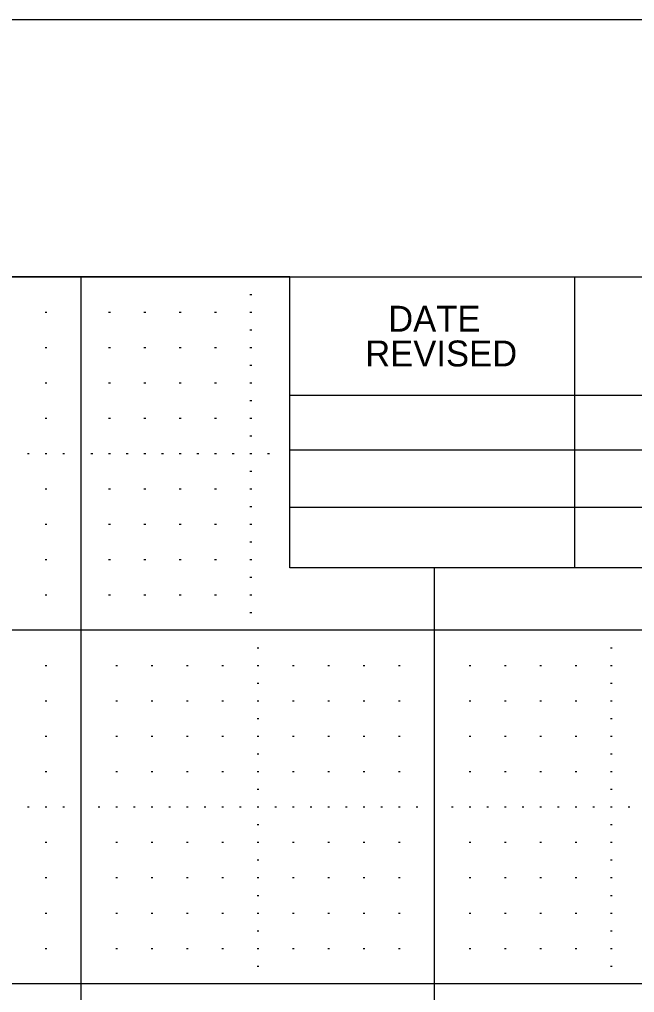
# Model space of a CAD drawing. Extents: x -1.6 to 32.4, y -1.9 to 21.6.
# Drawn here: x 25.633 to 27.374, y 18.52 to 21.273 of the extents above; entities that cross this region are included whole.
import ezdxf

# ---------------------------------------------------------------- set-up
doc = ezdxf.new("R2010")
doc.units = 0
for name, color, linetype in [('Level 1', 7, 'Continuous'), ('Level 4', 7, 'Continuous'), ('Level 5', 7, 'Continuous'), ('Level 61', 7, 'Continuous'), ('Level 63', 7, 'Continuous')]:
    doc.layers.add(name, color=color, linetype=linetype)

msp = doc.modelspace()

# ---------------------------------------------------------------- linework, layer by layer
at = {"layer": 'Level 1'}
for p, q in [((-0.001, 20.545), (31.617, 20.545)), ((26.3984, 19.7217), (26.3984, 20.545)), ((27.2051, 19.7217), (27.2051, 20.545)), ((26.3984, 20.21), (28.0268, 20.21)), ((26.3984, 20.055), (28.0268, 20.055)), ((26.3984, 19.8933), (28.0268, 19.8933)), ((31.6184, 19.7217), (26.3984, 19.7217))]:
    msp.add_line(p, q, dxfattribs=at)
at = {"layer": 'Level 4'}
for p, q in [((25.808, 0.545), (25.808, 20.545)), ((26.808, 0.545), (26.808, 19.7217)), ((31.617, 19.545), (-0.001, 19.545)), ((31.617, 18.545), (-0.001, 18.545))]:
    msp.add_line(p, q, dxfattribs=at)
at = {"layer": 'Level 5'}
for p, q in [((26.2855, 20.495), (26.2905, 20.495)), ((25.7055, 20.445), (25.7105, 20.445)), ((25.8855, 20.445), (25.8905, 20.445)), ((25.9855, 20.445), (25.9905, 20.445)), ((26.0855, 20.445), (26.0905, 20.445)), ((26.1855, 20.445), (26.1905, 20.445)), ((26.2855, 20.445), (26.2905, 20.445)), ((26.2855, 20.395), (26.2905, 20.395)), ((25.7055, 20.345), (25.7105, 20.345)), ((25.8855, 20.345), (25.8905, 20.345)), ((25.9855, 20.345), (25.9905, 20.345)), ((26.0855, 20.345), (26.0905, 20.345)), ((26.1855, 20.345), (26.1905, 20.345)), ((26.2855, 20.345), (26.2905, 20.345)), ((26.2855, 20.295), (26.2905, 20.295)), ((25.7055, 20.245), (25.7105, 20.245)), ((25.8855, 20.245), (25.8905, 20.245)), ((25.9855, 20.245), (25.9905, 20.245)), ((26.0855, 20.245), (26.0905, 20.245)), ((26.1855, 20.245), (26.1905, 20.245)), ((26.2855, 20.245), (26.2905, 20.245)), ((26.2855, 20.195), (26.2905, 20.195)), ((25.7055, 20.145), (25.7105, 20.145)), ((25.8855, 20.145), (25.8905, 20.145)), ((25.9855, 20.145), (25.9905, 20.145)), ((26.0855, 20.145), (26.0905, 20.145)), ((26.1855, 20.145), (26.1905, 20.145)), ((26.2855, 20.145), (26.2905, 20.145)), ((26.2855, 20.095), (26.2905, 20.095)), ((25.6555, 20.045), (25.6605, 20.045)), ((25.7055, 20.045), (25.7105, 20.045)), ((25.7555, 20.045), (25.7605, 20.045)), ((25.8355, 20.045), (25.8405, 20.045)), ((25.8855, 20.045), (25.8905, 20.045)), ((25.9355, 20.045), (25.9405, 20.045)), ((25.9855, 20.045), (25.9905, 20.045)), ((26.0355, 20.045), (26.0405, 20.045)), ((26.0855, 20.045), (26.0905, 20.045)), ((26.1355, 20.045), (26.1405, 20.045)), ((26.1855, 20.045), (26.1905, 20.045)), ((26.2355, 20.045), (26.2405, 20.045)), ((26.2855, 20.045), (26.2905, 20.045)), ((26.3355, 20.045), (26.3405, 20.045)), ((26.2855, 19.995), (26.2905, 19.995)), ((25.7055, 19.945), (25.7105, 19.945)), ((25.8855, 19.945), (25.8905, 19.945)), ((25.9855, 19.945), (25.9905, 19.945)), ((26.0855, 19.945), (26.0905, 19.945)), ((26.1855, 19.945), (26.1905, 19.945)), ((26.2855, 19.945), (26.2905, 19.945)), ((26.2855, 19.895), (26.2905, 19.895)), ((25.7055, 19.845), (25.7105, 19.845)), ((25.8855, 19.845), (25.8905, 19.845)), ((25.9855, 19.845), (25.9905, 19.845)), ((26.0855, 19.845), (26.0905, 19.845)), ((26.1855, 19.845), (26.1905, 19.845)), ((26.2855, 19.845), (26.2905, 19.845)), ((26.2855, 19.795), (26.2905, 19.795)), ((25.7055, 19.745), (25.7105, 19.745)), ((25.8855, 19.745), (25.8905, 19.745)), ((25.9855, 19.745), (25.9905, 19.745)), ((26.0855, 19.745), (26.0905, 19.745)), ((26.1855, 19.745), (26.1905, 19.745)), ((26.2855, 19.745), (26.2905, 19.745)), ((26.2855, 19.695), (26.2905, 19.695)), ((25.7055, 19.645), (25.7105, 19.645)), ((25.8855, 19.645), (25.8905, 19.645)), ((25.9855, 19.645), (25.9905, 19.645)), ((26.0855, 19.645), (26.0905, 19.645)), ((26.1855, 19.645), (26.1905, 19.645)), ((26.2855, 19.645), (26.2905, 19.645)), ((26.2855, 19.595), (26.2905, 19.595)), ((26.3055, 19.495), (26.3105, 19.495)), ((27.3055, 19.495), (27.3105, 19.495)), ((25.7055, 19.445), (25.7105, 19.445)), ((25.9055, 19.445), (25.9105, 19.445)), ((26.0055, 19.445), (26.0105, 19.445)), ((26.1055, 19.445), (26.1105, 19.445)), ((26.2055, 19.445), (26.2105, 19.445)), ((26.3055, 19.445), (26.3105, 19.445)), ((26.4055, 19.445), (26.4105, 19.445)), ((26.5055, 19.445), (26.5105, 19.445)), ((26.6055, 19.445), (26.6105, 19.445)), ((26.7055, 19.445), (26.7105, 19.445)), ((26.9055, 19.445), (26.9105, 19.445)), ((27.0055, 19.445), (27.0105, 19.445)), ((27.1055, 19.445), (27.1105, 19.445)), ((27.2055, 19.445), (27.2105, 19.445)), ((27.3055, 19.445), (27.3105, 19.445)), ((26.3055, 19.395), (26.3105, 19.395)), ((27.3055, 19.395), (27.3105, 19.395)), ((25.7055, 19.345), (25.7105, 19.345)), ((25.9055, 19.345), (25.9105, 19.345)), ((26.0055, 19.345), (26.0105, 19.345)), ((26.1055, 19.345), (26.1105, 19.345)), ((26.2055, 19.345), (26.2105, 19.345)), ((26.3055, 19.345), (26.3105, 19.345)), ((26.4055, 19.345), (26.4105, 19.345)), ((26.5055, 19.345), (26.5105, 19.345)), ((26.6055, 19.345), (26.6105, 19.345)), ((26.7055, 19.345), (26.7105, 19.345)), ((26.9055, 19.345), (26.9105, 19.345)), ((27.0055, 19.345), (27.0105, 19.345)), ((27.1055, 19.345), (27.1105, 19.345)), ((27.2055, 19.345), (27.2105, 19.345)), ((27.3055, 19.345), (27.3105, 19.345)), ((26.3055, 19.295), (26.3105, 19.295)), ((27.3055, 19.295), (27.3105, 19.295)), ((25.7055, 19.245), (25.7105, 19.245)), ((25.9055, 19.245), (25.9105, 19.245)), ((26.0055, 19.245), (26.0105, 19.245)), ((26.1055, 19.245), (26.1105, 19.245)), ((26.2055, 19.245), (26.2105, 19.245)), ((26.3055, 19.245), (26.3105, 19.245)), ((26.4055, 19.245), (26.4105, 19.245)), ((26.5055, 19.245), (26.5105, 19.245)), ((26.6055, 19.245), (26.6105, 19.245)), ((26.7055, 19.245), (26.7105, 19.245)), ((26.9055, 19.245), (26.9105, 19.245)), ((27.0055, 19.245), (27.0105, 19.245)), ((27.1055, 19.245), (27.1105, 19.245)), ((27.2055, 19.245), (27.2105, 19.245)), ((27.3055, 19.245), (27.3105, 19.245)), ((26.3055, 19.195), (26.3105, 19.195)), ((27.3055, 19.195), (27.3105, 19.195)), ((25.7055, 19.145), (25.7105, 19.145)), ((25.9055, 19.145), (25.9105, 19.145)), ((26.0055, 19.145), (26.0105, 19.145)), ((26.1055, 19.145), (26.1105, 19.145)), ((26.2055, 19.145), (26.2105, 19.145)), ((26.3055, 19.145), (26.3105, 19.145)), ((26.4055, 19.145), (26.4105, 19.145)), ((26.5055, 19.145), (26.5105, 19.145)), ((26.6055, 19.145), (26.6105, 19.145)), ((26.7055, 19.145), (26.7105, 19.145)), ((26.9055, 19.145), (26.9105, 19.145)), ((27.0055, 19.145), (27.0105, 19.145)), ((27.1055, 19.145), (27.1105, 19.145)), ((27.2055, 19.145), (27.2105, 19.145)), ((27.3055, 19.145), (27.3105, 19.145)), ((26.3055, 19.095), (26.3105, 19.095)), ((27.3055, 19.095), (27.3105, 19.095)), ((25.6555, 19.045), (25.6605, 19.045)), ((25.7055, 19.045), (25.7105, 19.045)), ((25.7555, 19.045), (25.7605, 19.045)), ((25.8555, 19.045), (25.8605, 19.045)), ((25.9055, 19.045), (25.9105, 19.045)), ((25.9555, 19.045), (25.9605, 19.045)), ((26.0055, 19.045), (26.0105, 19.045)), ((26.0555, 19.045), (26.0605, 19.045)), ((26.1055, 19.045), (26.1105, 19.045)), ((26.1555, 19.045), (26.1605, 19.045)), ((26.2055, 19.045), (26.2105, 19.045)), ((26.2555, 19.045), (26.2605, 19.045)), ((26.3055, 19.045), (26.3105, 19.045)), ((26.3555, 19.045), (26.3605, 19.045)), ((26.4055, 19.045), (26.4105, 19.045)), ((26.4555, 19.045), (26.4605, 19.045)), ((26.5055, 19.045), (26.5105, 19.045)), ((26.5555, 19.045), (26.5605, 19.045)), ((26.6055, 19.045), (26.6105, 19.045)), ((26.6555, 19.045), (26.6605, 19.045)), ((26.7055, 19.045), (26.7105, 19.045)), ((26.7555, 19.045), (26.7605, 19.045)), ((26.8555, 19.045), (26.8605, 19.045)), ((26.9055, 19.045), (26.9105, 19.045)), ((26.9555, 19.045), (26.9605, 19.045)), ((27.0055, 19.045), (27.0105, 19.045)), ((27.0555, 19.045), (27.0605, 19.045)), ((27.1055, 19.045), (27.1105, 19.045)), ((27.1555, 19.045), (27.1605, 19.045)), ((27.2055, 19.045), (27.2105, 19.045)), ((27.2555, 19.045), (27.2605, 19.045)), ((27.3055, 19.045), (27.3105, 19.045)), ((27.3555, 19.045), (27.3605, 19.045)), ((26.3055, 18.995), (26.3105, 18.995)), ((27.3055, 18.995), (27.3105, 18.995)), ((25.7055, 18.945), (25.7105, 18.945)), ((25.9055, 18.945), (25.9105, 18.945)), ((26.0055, 18.945), (26.0105, 18.945)), ((26.1055, 18.945), (26.1105, 18.945)), ((26.2055, 18.945), (26.2105, 18.945)), ((26.3055, 18.945), (26.3105, 18.945)), ((26.4055, 18.945), (26.4105, 18.945)), ((26.5055, 18.945), (26.5105, 18.945)), ((26.6055, 18.945), (26.6105, 18.945)), ((26.7055, 18.945), (26.7105, 18.945)), ((26.9055, 18.945), (26.9105, 18.945)), ((27.0055, 18.945), (27.0105, 18.945)), ((27.1055, 18.945), (27.1105, 18.945)), ((27.2055, 18.945), (27.2105, 18.945)), ((27.3055, 18.945), (27.3105, 18.945)), ((26.3055, 18.895), (26.3105, 18.895)), ((27.3055, 18.895), (27.3105, 18.895)), ((25.7055, 18.845), (25.7105, 18.845)), ((25.9055, 18.845), (25.9105, 18.845)), ((26.0055, 18.845), (26.0105, 18.845)), ((26.1055, 18.845), (26.1105, 18.845)), ((26.2055, 18.845), (26.2105, 18.845)), ((26.3055, 18.845), (26.3105, 18.845)), ((26.4055, 18.845), (26.4105, 18.845)), ((26.5055, 18.845), (26.5105, 18.845)), ((26.6055, 18.845), (26.6105, 18.845)), ((26.7055, 18.845), (26.7105, 18.845)), ((26.9055, 18.845), (26.9105, 18.845)), ((27.0055, 18.845), (27.0105, 18.845)), ((27.1055, 18.845), (27.1105, 18.845)), ((27.2055, 18.845), (27.2105, 18.845)), ((27.3055, 18.845), (27.3105, 18.845)), ((26.3055, 18.795), (26.3105, 18.795)), ((27.3055, 18.795), (27.3105, 18.795)), ((25.7055, 18.745), (25.7105, 18.745)), ((25.9055, 18.745), (25.9105, 18.745)), ((26.0055, 18.745), (26.0105, 18.745)), ((26.1055, 18.745), (26.1105, 18.745)), ((26.2055, 18.745), (26.2105, 18.745)), ((26.3055, 18.745), (26.3105, 18.745)), ((26.4055, 18.745), (26.4105, 18.745)), ((26.5055, 18.745), (26.5105, 18.745)), ((26.6055, 18.745), (26.6105, 18.745)), ((26.7055, 18.745), (26.7105, 18.745)), ((26.9055, 18.745), (26.9105, 18.745)), ((27.0055, 18.745), (27.0105, 18.745)), ((27.1055, 18.745), (27.1105, 18.745)), ((27.2055, 18.745), (27.2105, 18.745)), ((27.3055, 18.745), (27.3105, 18.745)), ((26.3055, 18.695), (26.3105, 18.695)), ((27.3055, 18.695), (27.3105, 18.695)), ((25.7055, 18.645), (25.7105, 18.645)), ((25.9055, 18.645), (25.9105, 18.645)), ((26.0055, 18.645), (26.0105, 18.645)), ((26.1055, 18.645), (26.1105, 18.645)), ((26.2055, 18.645), (26.2105, 18.645)), ((26.3055, 18.645), (26.3105, 18.645)), ((26.4055, 18.645), (26.4105, 18.645)), ((26.5055, 18.645), (26.5105, 18.645)), ((26.6055, 18.645), (26.6105, 18.645)), ((26.7055, 18.645), (26.7105, 18.645)), ((26.9055, 18.645), (26.9105, 18.645)), ((27.0055, 18.645), (27.0105, 18.645)), ((27.1055, 18.645), (27.1105, 18.645)), ((27.2055, 18.645), (27.2105, 18.645)), ((27.3055, 18.645), (27.3105, 18.645)), ((26.3055, 18.595), (26.3105, 18.595)), ((27.3055, 18.595), (27.3105, 18.595))]:
    msp.add_line(p, q, dxfattribs=at)
at = {"layer": 'Level 61'}
msp.add_lwpolyline([(0.808, 0.545), (30.808, 0.545), (30.8079, 19.7222), (26.3984, 19.7217), (26.3984, 19.7217), (26.3984, 19.7217), (26.3984, 19.7217), (26.3984, 19.7217), (26.3984, 20.545), (26.3984, 20.545), (26.3984, 20.545), (0.808, 20.545)], close=True, dxfattribs=at)
at = {"layer": 'Level 63'}
msp.add_lwpolyline([(-1.598, 21.273), (32.402, 21.273), (32.402, -0.727), (-1.598, -0.727)], close=True, dxfattribs=at)

# ---------------------------------------------------------------- texts
at = {"layer": 'Level 1'}
for s, p in [('DATE', (26.6766, 20.3897)), ('REVISED', (26.6116, 20.2914))]:
    msp.add_text(s, height=0.07327, dxfattribs=at).set_placement(p)

doc.saveas('drawing.dxf')
